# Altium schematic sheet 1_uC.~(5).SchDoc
size 414 x 293 mm; SheetNumber: 1; SheetTotal: 4
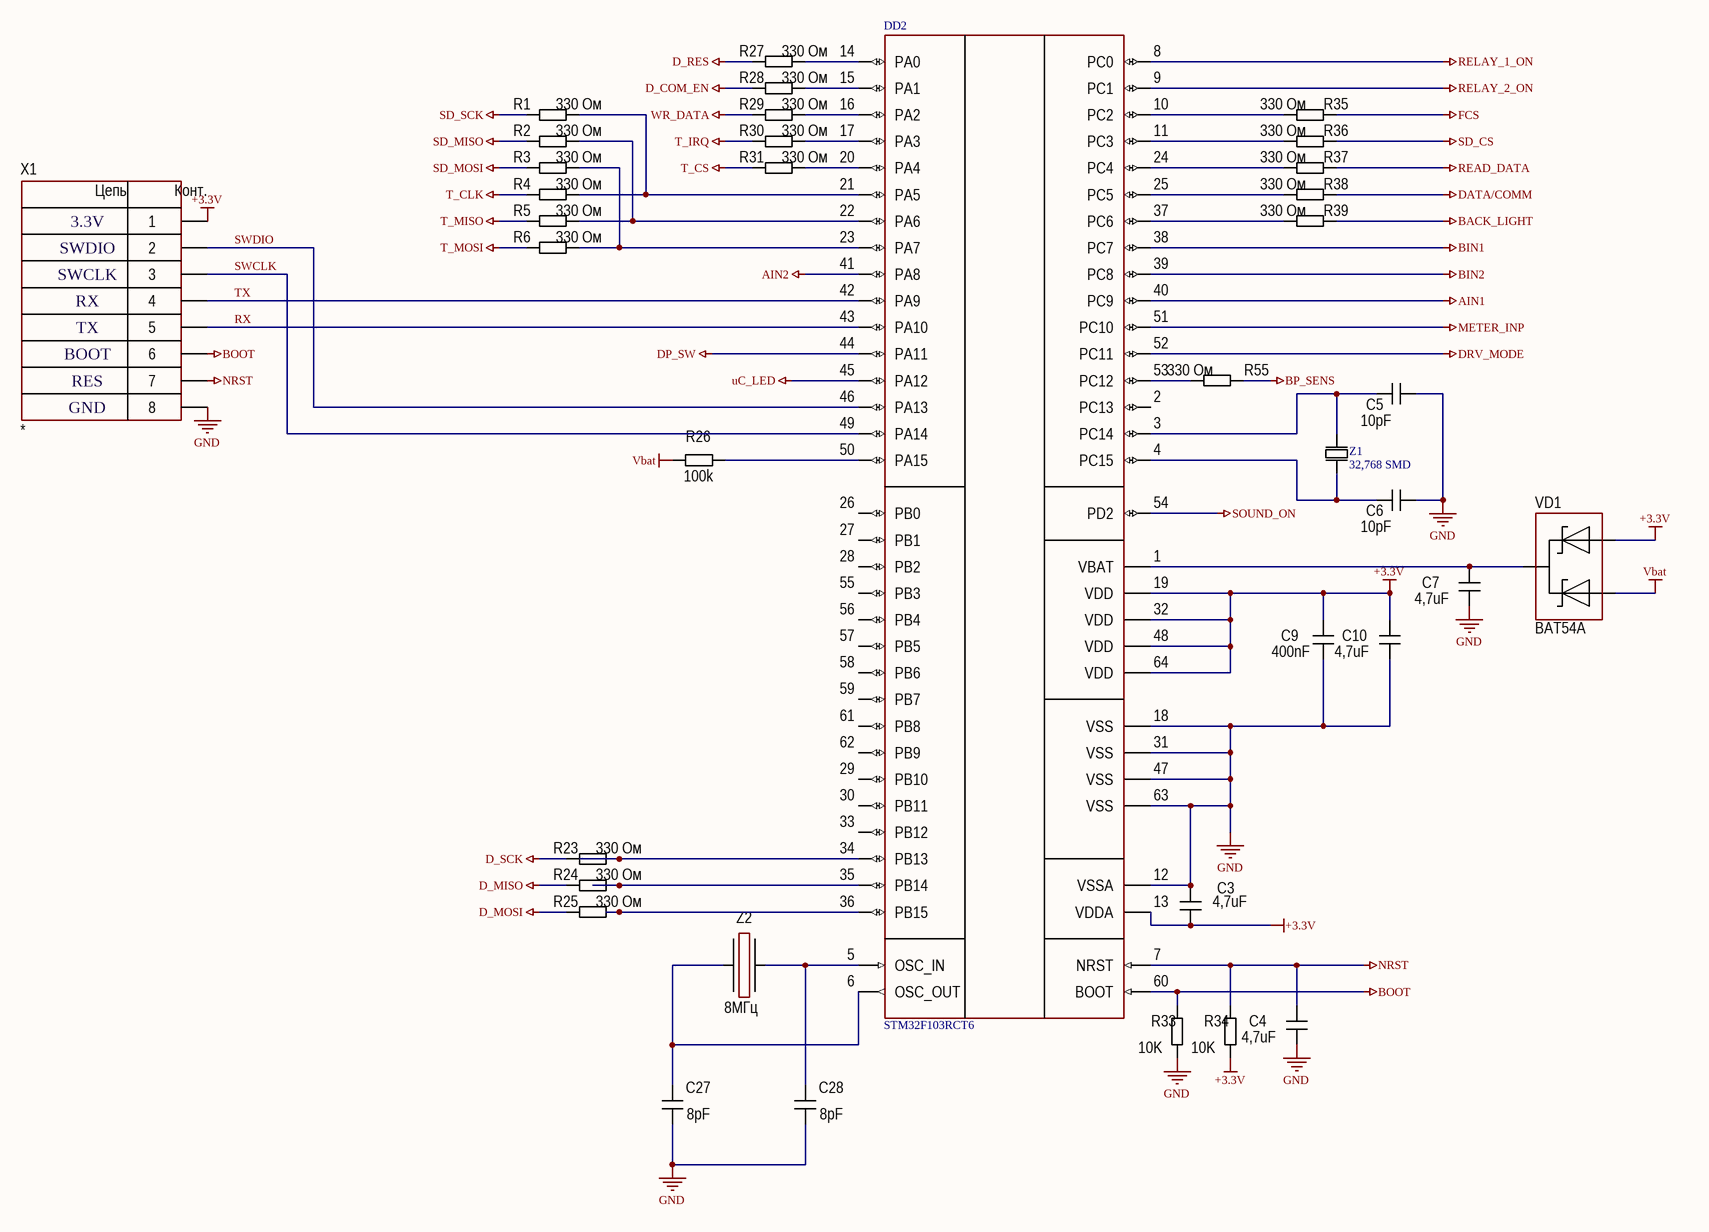
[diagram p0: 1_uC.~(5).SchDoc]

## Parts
C3  4,7uF  [CH0402C]
C4  4,7uF  [CH0402C]
C5  10pF  [CH0402C]
C6  10pF  [CH0402C]
C7  4,7uF  [CH0402C]
C9  400nF  [CH0402C]
C10  4,7uF  [CH0402C]
C27  8pF  [CH0402C]
C28  8pF  [CH0402C]
DD2  STM32F103RCT6  [64-LQFP]
R1  330 Ом  [CH0603R]
R2  330 Ом  [CH0603R]
R3  330 Ом  [CH0603R]
R4  330 Ом  [CH0603R]
R5  330 Ом  [CH0603R]
R6  330 Ом  [CH0603R]
R23  330 Ом  [CH0603R]
R24  330 Ом  [CH0603R]
R25  330 Ом  [CH0603R]
R26  100k  [CH0603R]
R27  330 Ом  [CH0603R]
R28  330 Ом  [CH0603R]
R29  330 Ом  [CH0603R]
R30  330 Ом  [CH0603R]
R31  330 Ом  [CH0603R]
R33  10K  [CH0805R]
R34  10K  [CH0805R]
R35  330 Ом  [CH0603R]
R36  330 Ом  [CH0603R]
R37  330 Ом  [CH0603R]
R38  330 Ом  [CH0603R]
R39  330 Ом  [CH0603R]
R55  330 Ом  [CH0603R]
VD1  BAT54A  [SOT23_123]
X1  *  [CON: PLS-8]
Z1  32,768 SMD  [SMD 32.768KHz]
Z2  8МГц  [OSC: ABM3]

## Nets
+3.3V: C3.1 C9.1 C10.2 DD2.13(VDDA) DD2.19(VDD) DD2.32(VDD) DD2.48(VDD) DD2.64(VDD) R34.1 VD1.1 X1.1
AIN1: DD2.40(PC9)
AIN2: DD2.41(PA8)
BACK_LIGHT: R39.1
BIN1: DD2.38(PC7)
BIN2: DD2.39(PC8)
BOOT: DD2.60(BOOT) R33.2 X1.6
BP_SENS: R55.1
D_COM_EN: R28.1
D_MISO: R24.1
D_MOSI: R25.1
D_RES: R27.1
D_SCK: R23.1
DATA/COMM: R38.1
DP_SW: DD2.44(PA11)
DRV_MODE: DD2.52(PC11)
FCS: R35.1
GND: C3.2 C4.1 C5.2 C6.1 C7.1 C9.2 C10.1 C27.1 C28.1 DD2.12(VSSA) DD2.18(VSS) DD2.31(VSS) DD2.47(VSS) DD2.63(VSS) R33.1 X1.8
METER_INP: DD2.51(PC10)
NRST: C4.2 DD2.7(NRST) R34.2 X1.7
READ_DATA: R37.1
RELAY_1_ON: DD2.8(PC0)
RELAY_2_ON: DD2.9(PC1)
SD_CS: R36.1
SD_MISO: R2.1
SD_MOSI: R3.1
SD_SCK: R1.1
SOUND_ON: DD2.54(PD2)
T_CLK: R4.1
T_CS: R31.1
T_IRQ: R30.1
T_MISO: R5.1
T_MOSI: R6.1
uC_LED: DD2.45(PA12)
Vbat: R26.1 VD1.3
WR_DATA: R29.1
RX: DD2.43(PA10) X1.5
SWCLK: DD2.49(PA14) X1.3
SWDIO: DD2.46(PA13) X1.2
TX: DD2.42(PA9) X1.4
NetC5_1: C5.1 DD2.3(PC14) Z1.1
NetC6_2: C6.2 DD2.4(PC15) Z1.2
NetC7_2: C7.2 DD2.1(VBAT) VD1.2
NetC27_2: C27.2 DD2.6(OSC_OUT) Z2.1
NetC28_2: C28.2 DD2.5(OSC_IN) Z2.3
NetDD2_10: DD2.10(PC2) R35.2
NetDD2_11: DD2.11(PC3) R36.2
NetDD2_14: DD2.14(PA0) R27.2
NetDD2_15: DD2.15(PA1) R28.2
NetDD2_16: DD2.16(PA2) R29.2
NetDD2_17: DD2.17(PA3) R30.2
NetDD2_20: DD2.20(PA4) R31.2
NetDD2_21: DD2.21(PA5) R1.2 R4.2
NetDD2_22: DD2.22(PA6) R2.2 R5.2
NetDD2_23: DD2.23(PA7) R3.2 R6.2
NetDD2_24: DD2.24(PC4) R37.2
NetDD2_25: DD2.25(PC5) R38.2
NetDD2_34: DD2.34(PB13) R23.2
NetDD2_35: DD2.35(PB14) R24.2
NetDD2_36: DD2.36(PB15) R25.2
NetDD2_37: DD2.37(PC6) R39.2
NetDD2_50: DD2.50(PA15) R26.2
NetDD2_53: DD2.53(PC12) R55.2

Not connected (* = marked no-connect by the designer): DD2 2(PC13) 26(PB0) 27(PB1) 28(PB2) 29(PB10) 30(PB11) 33(PB12) 55(PB3) 56(PB4) 57(PB5) 58(PB6) 59(PB7) 61(PB8) 62(PB9)

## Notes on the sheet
- 3.3V
- SWDIO
- SWCLK
- RX
- TX
- BOOT
- RES
- GND

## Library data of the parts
C3-C6 C9 C10 C27 C28 = Capacitor: 0402
C7 = Capacitor
DD2 = STM32F103RCT6: Cortex-M3 (64-LQFP)
R1-R6 R23-R31 R35-R39 R55 = Resistor: 0603
R33 R34 = Resistor: 0805
VD1 = Diod Schottky Array v.1: SOT-23
X1 = 8-Connector: Pin header 8
Z1 = Kvarc_32,768: 32,768 kHz SMD 8mm x 3.8mm 12,5pF
Z2 = Oscillator: NX5032GA-8MHz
